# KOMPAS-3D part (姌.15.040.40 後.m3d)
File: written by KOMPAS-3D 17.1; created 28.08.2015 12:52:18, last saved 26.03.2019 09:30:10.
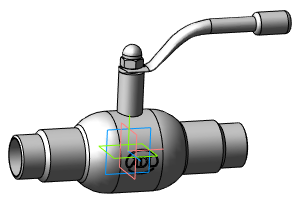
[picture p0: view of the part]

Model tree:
1. Операция без истории:7  (labels: Сталь 20  ГОСТ 1050-88)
